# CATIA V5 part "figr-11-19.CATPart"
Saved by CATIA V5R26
Part number: Part1
Bounding box of the stored display mesh (mm): x -112.891 to 155.069, y -166 to 177, z -20.381 to 17.354
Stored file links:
  D:\_Deepak\CATIA\CATIA V5-6R2016_Deepak\Resources\Part files\Partfiles\c11_catia_v5_6r2016_prt\figr-11-19.CATPart
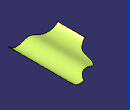
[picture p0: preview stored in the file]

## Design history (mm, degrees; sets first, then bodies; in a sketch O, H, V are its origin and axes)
Set1
  Sketch1 on zx-plane, origin (0, 0, 0), H (-1, 0, 0), V (0, 0, 1)
    spline S1 through (-155.0686, 17.3535) (-88.0787, 0) (-53.6625, 10.5338) (-6.5258, 0) (112.8909, 0)
    point P1 (-88.0787, 0)
    point P2 (-6.5258, 0)
    point P3 (112.8909, 0)
    coincidence: P1 H, P2 H, P3 H
  Extrude1: Element1 Sketch1, Lim1 177, Lim2 166, Direction zx-plane
  Sketch2 on xy-plane, origin (0, 0, 0), H (1, 0, 0), V (0, 1, 0)
    spline S1 through (-167.4699, -22.0252) (-66.0833, 12.4475) (-43.2893, 80.3989) (-11.0164, 123.7609) (37.393, 134.2276) (93.5198, 192.542)
  Extrude2: Element1 Sketch2, Lim1 94, Lim2 109, Direction xy-plane
  Trim1: Element1 Extrude1, Element2 Extrude2
  DatumSurface1
  DatumSurface2
  StUntrimFeature1 "CATStUntrimFeatureName": SpecToUntrim DatumSurface1
Body1 (main body)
